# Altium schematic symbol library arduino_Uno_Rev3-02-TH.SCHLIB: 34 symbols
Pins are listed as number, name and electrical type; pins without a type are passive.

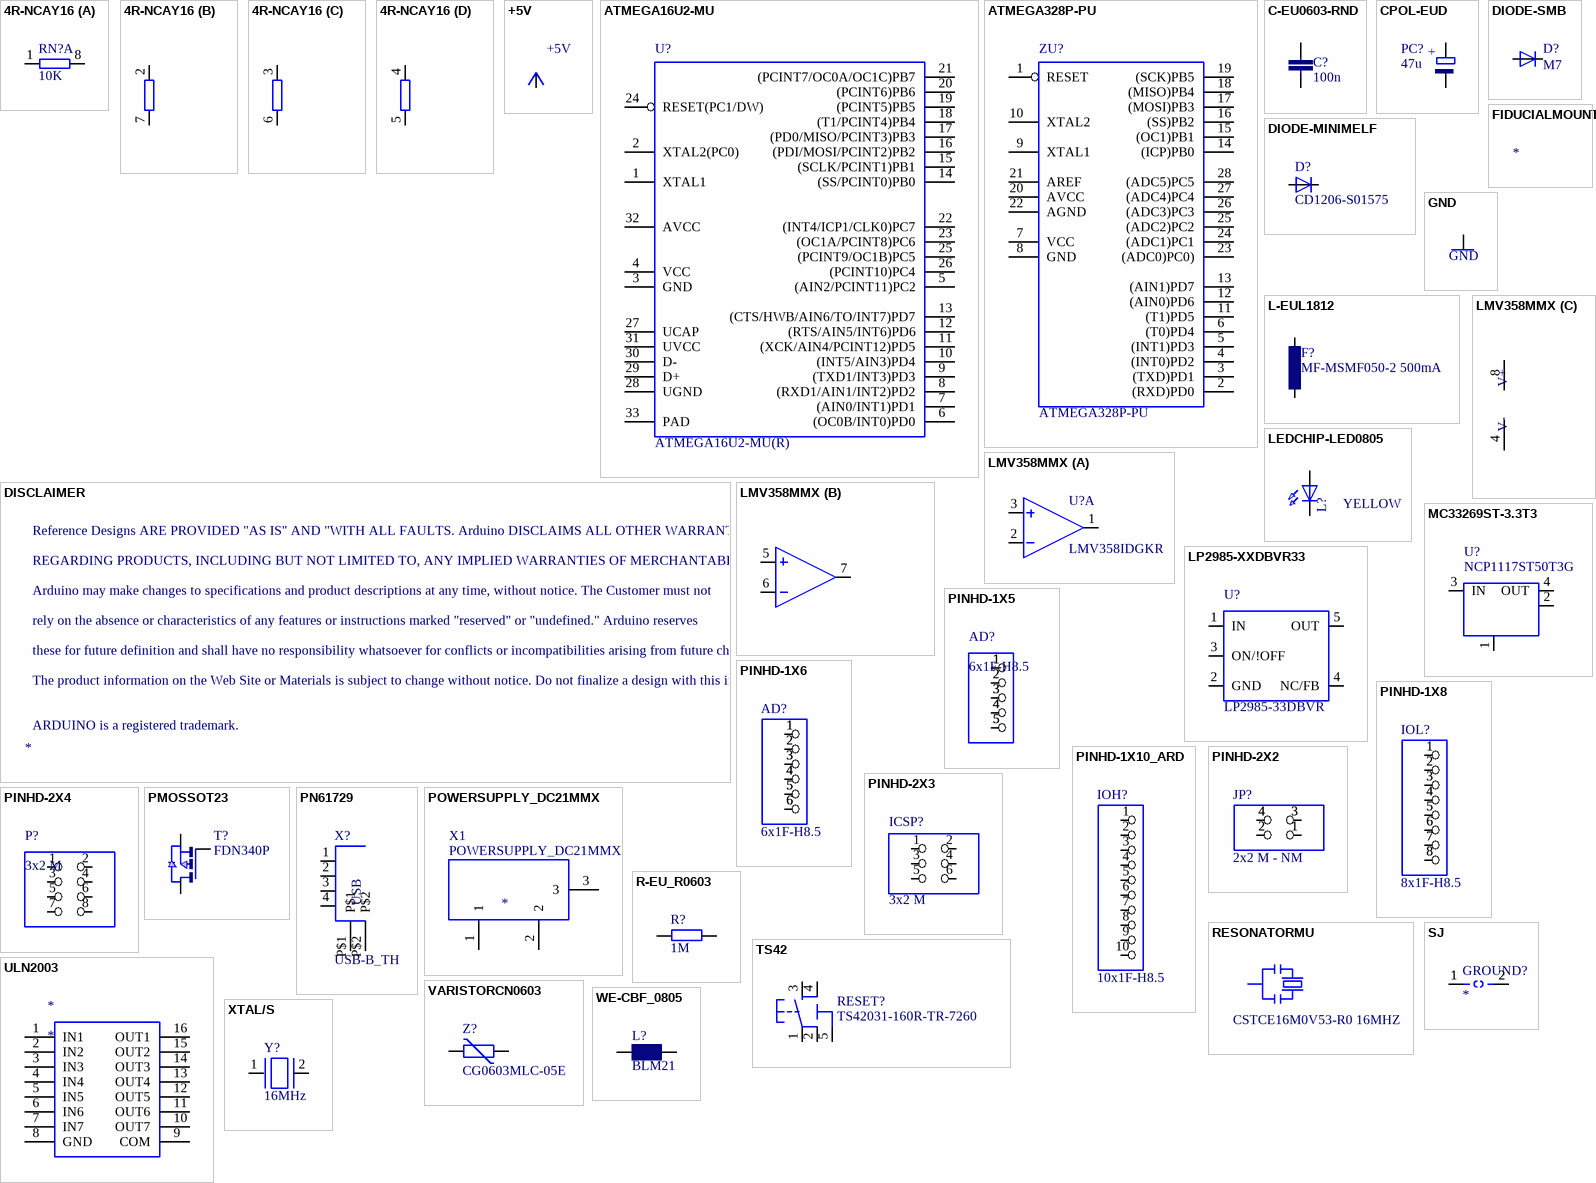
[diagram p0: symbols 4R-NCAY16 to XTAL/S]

## 4R-NCAY16
designator RN?, comment 10K
footprint CAY16
part A pins: 1, 8 2
part B pins: 2 1, 7 2
part C pins: 3 1, 6 2
part D pins: 4 1, 5 2
2 alternate drawings of the same symbol

## +5V
designator P+?
pins: 0 +5V
2 alternate drawings of the same symbol

## ATMEGA16U2-MU
designator U?, comment ATMEGA16U2-MU(R)
footprint MLF32
pins: 1 XTAL1, 2 XTAL2(PC0), 3 GND, 4 VCC, 5 (AIN2/PCINT11)PC2, 6 (OC0B/INT0)PD0, 7 (AIN0/INT1)PD1, 8 (RXD1/AIN1/INT2)PD2, 9 (TXD1/INT3)PD3, 10 (INT5/AIN3)PD4, 11 (XCK/AIN4/PCINT12)PD5, 12 (RTS/AIN5/INT6)PD6, 13 (CTS/HWB/AIN6/TO/INT7)PD7, 14 (SS/PCINT0)PB0, 15 (SCLK/PCINT1)PB1, 16 (PDI/MOSI/PCINT2)PB2, 17 (PD0/MISO/PCINT3)PB3, 18 (T1/PCINT4)PB4, 19 (PCINT5)PB5, 20 (PCINT6)PB6, 21 (PCINT7/OC0A/OC1C)PB7, 22 (INT4/ICP1/CLK0)PC7, 23 (OC1A/PCINT8)PC6, 24 RESET(PC1/DW), 25 (PCINT9/OC1B)PC5, 26 (PCINT10)PC4, 27 UCAP, 28 UGND, 29 D+, 30 D-, 31 UVCC, 32 AVCC, 33 PAD
2 alternate drawings of the same symbol

## ATMEGA328P-PU
designator ZU?
footprint DIL28-3
pins: 1 RESET, 2 (RXD)PD0, 3 (TXD)PD1, 4 (INT0)PD2, 5 (INT1)PD3, 6 (T0)PD4, 7 VCC, 8 GND, 9 XTAL1, 10 XTAL2, 11 (T1)PD5, 12 (AIN0)PD6, 13 (AIN1)PD7, 14 (ICP)PB0, 15 (OC1)PB1, 16 (SS)PB2, 17 (MOSI)PB3, 18 (MISO)PB4, 19 (SCK)PB5, 20 AVCC, 21 AREF, 22 AGND, 23 (ADC0)PC0), 24 (ADC1)PC1, 25 (ADC2)PC2, 26 (ADC3)PC3, 27 (ADC4)PC4, 28 (ADC5)PC5
2 alternate drawings of the same symbol

## C-EU0603-RND
designator C?, comment 100n
footprint R0603-ROUND
pins: 1, 2
2 alternate drawings of the same symbol

## CPOL-EUD
designator PC?, comment 47u
footprint PANASONIC_D
pins: +, -
2 alternate drawings of the same symbol

## DIODE-MINIMELF
designator D?, comment CD1206-S01575
footprint MINIMELF
pins: A, C
2 alternate drawings of the same symbol

## DIODE-SMB
designator D?, comment M7
footprint SMB
pins: A, C
2 alternate drawings of the same symbol

## DISCLAIMER
designator U$?
footprint DISCLAIMER
2 alternate drawings of the same symbol

## FIDUCIALMOUNT
designator FD?
footprint FIDUCIA-MOUNT

## GND
designator GND?
pins: 0 GND
2 alternate drawings of the same symbol

## L-EUL1812
designator F?, comment MF-MSMF050-2 500mA
footprint L1812
pins: 1, 2
2 alternate drawings of the same symbol

## LEDCHIP-LED0805
designator L?, comment YELLOW
footprint CHIP-LED0805
pins: A, C
2 alternate drawings of the same symbol

## LMV358MMX
designator U?, comment LMV358IDGKR
footprint MSOP08
part A pins: 1 OUT, 2 -IN, 3 +IN
part B pins: 5 +IN, 6 -IN, 7 OUT
part C pins: 4 V-, 8 V+
2 alternate drawings of the same symbol

## LP2985-XXDBVR33
designator U?, comment LP2985-33DBVR
footprint SOT23-DBV
pins: 1 IN, 2 GND, 3 ON/!OFF, 4 NC/FB, 5 OUT
2 alternate drawings of the same symbol

## MC33269ST-3.3T3
designator U?, comment NCP1117ST50T3G
footprint SOT223
pins: 1 GND/ADJ, 2 OUT@1, 3 IN, 4 OUT
2 alternate drawings of the same symbol

## PINHD-1X5
designator AD?, comment 6x1F-H8.5
footprint 1X05
pins: 1, 1, 1, 2, 2, 2, 3, 3, 3, 4, 4, 4, 5, 5, 5

## PINHD-1X6
designator AD?, comment 6x1F-H8.5
footprint 1X06
pins: 1, 1, 1, 2, 2, 2, 3, 3, 3, 4, 4, 4, 5, 5, 5, 6, 6, 6
2 alternate drawings of the same symbol

## PINHD-1X8
designator IOL?, comment 8x1F-H8.5
footprint 1X08
pins: 1, 1, 2, 2, 3, 3, 4, 4, 5, 5, 6, 6, 7, 7, 8, 8
2 alternate drawings of the same symbol

## PINHD-1X10_ARD
designator IOH?, comment 10x1F-H8.5
footprint 1X10@1
pins: 1, 2, 3, 4, 5, 6, 7, 8, 9, 10
2 alternate drawings of the same symbol

## PINHD-2X2
designator JP?, comment 2x2 M - NM
footprint 2X02
pins: 1, 1, 2, 2, 3, 3, 4, 4
2 alternate drawings of the same symbol

## PINHD-2X3
designator ICSP?, comment 3x2 M
footprint 2X03
pins: 1, 2, 3, 4, 5, 6
2 alternate drawings of the same symbol

## PINHD-2X4
designator P?, comment 3x2 M
footprint 2X04
pins: 1, 2, 3, 4, 5, 6, 7, 8

## PMOSSOT23
designator T?, comment FDN340P
footprint SOT-23
pins: 1 D, 2 S, 3 G
2 alternate drawings of the same symbol

## PN61729
designator X?, comment USB-B_TH
footprint PN61729
pins: 1, 2, 3, 4, P$1, P$2
2 alternate drawings of the same symbol

## POWERSUPPLY_DC21MMX
designator X?
footprint POWERSUPPLY_DC-21MM
pins: 1, 2, 3
2 alternate drawings of the same symbol

## R-EU_R0603
designator R?, comment 1M
footprint R0603-ROUND
pins: 1, 2
2 alternate drawings of the same symbol

## RESONATORMU
designator Y?, comment CSTCE16M0V53-R0 16MHZ
footprint RESONATOR
pins: 1, 2, 3
2 alternate drawings of the same symbol

## SJ
designator GROUND?
footprint SJ
pins: 1, 1, 2, 2
2 alternate drawings of the same symbol

## TS42
designator RESET?, comment TS42031-160R-TR-7260
footprint TS42
pins: 1, 2, 3, 4, 5 5-GND
2 alternate drawings of the same symbol

## ULN2003
designator *
footprint sop16
pins: 1 IN1, 2 IN2, 3 IN3, 4 IN4, 5 IN5, 6 IN6, 7 IN7, 8 GND, 9 COM, 10 OUT7, 11 OUT6, 12 OUT5, 13 OUT4, 14 OUT3, 15 OUT2, 16 OUT1

## VARISTORCN0603
designator Z?, comment CG0603MLC-05E
footprint CT/CN0603
pins: 1, 2
2 alternate drawings of the same symbol

## WE-CBF_0805
designator L?, comment BLM21
footprint 0805
pins: 1, 2
2 alternate drawings of the same symbol

## XTAL/S
designator Y?, comment 16MHz
footprint QS
pins: 1, 2
2 alternate drawings of the same symbol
